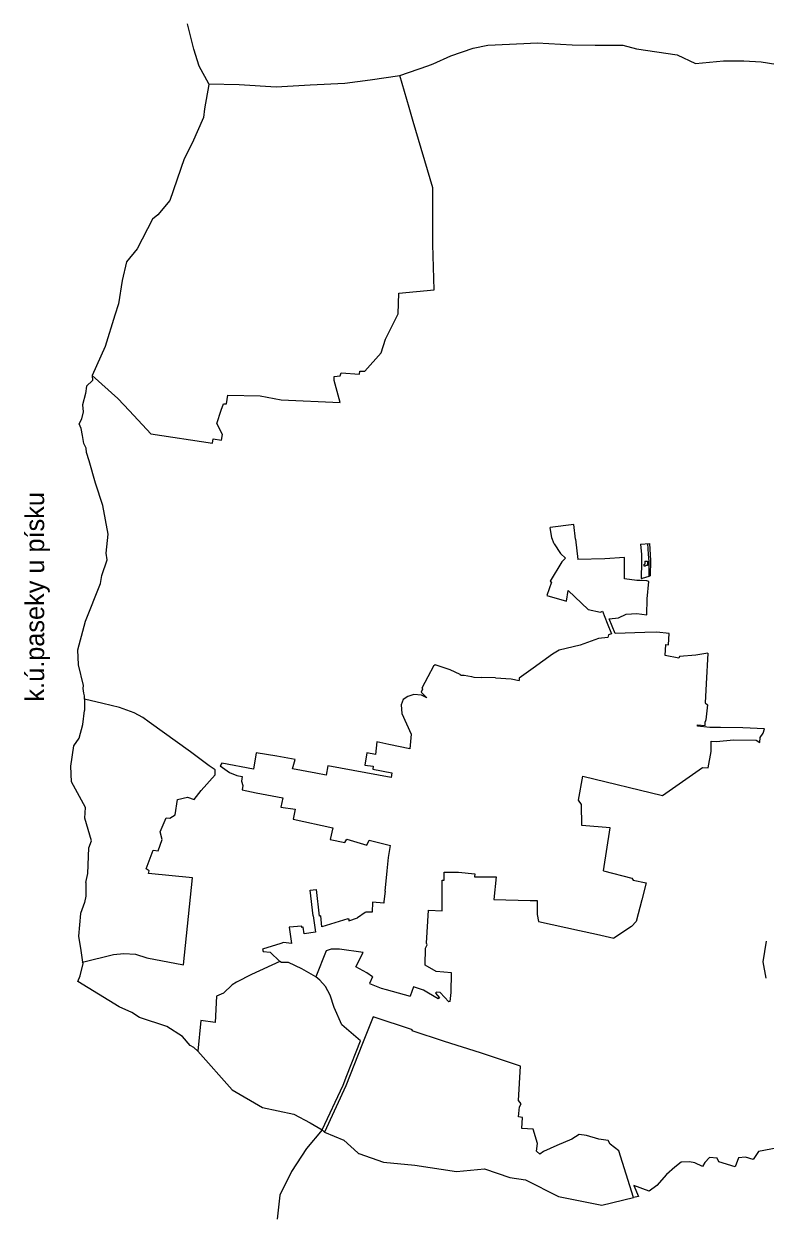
# Model space of a CAD drawing. Extents: x -764981 to -759318, y -1137368 to -1131930.
# Drawn here: x -764981 to -763217, y -1134773 to -1131930 of the extents above; entities that cross this region are included whole.
import ezdxf

# ---------------------------------------------------------------- set-up
doc = ezdxf.new("R2010")
doc.units = 0
for name, color, linetype in [('Vrstva 40', 7, 'Continuous'), ('Vrstva 41', 7, 'Continuous'), ('Vrstva 42', 7, 'Continuous'), ('Vrstva 43', 7, 'Continuous'), ('Vrstva 44', 7, 'Continuous'), ('Vrstva 45', 7, 'Continuous')]:
    doc.layers.add(name, color=color, linetype=linetype)

msp = doc.modelspace()

# ---------------------------------------------------------------- linework, layer by layer
at = {"layer": 'Vrstva 40'}
for p, q in [((-763668, -1133155.9), (-763662.7, -1133204.2)), ((-764509.7, -1133688.5), (-764513.8, -1133695.3)), ((-764461.7, -1133752.2), (-764428, -1133759.7)), ((-764369.8, -1134117.9), (-764413, -1134131.2)), ((-764413, -1134131.2), (-764411.2, -1134137)), ((-764411.2, -1134137), (-764394.7, -1134138.4)), ((-764394.7, -1134138.4), (-764372, -1134160.7)), ((-764261.9, -1134135.1), (-764285.9, -1134197.1)), ((-764054, -1134221.1), (-764061.9, -1134243.1))]:
    msp.add_line(p, q, dxfattribs=at)
for points in [[(-763668, -1133155.9), (-763672.7, -1133120.8), (-763728.8, -1133128.2)], [(-763719.5, -1133166.6), (-763724.5, -1133152.5), (-763728.8, -1133128.2)], [(-763719.5, -1133166.6), (-763703.7, -1133189.7), (-763692.5, -1133201), (-763701.1, -1133209.4), (-763728.7, -1133255.4)], [(-763552, -1133207.3), (-763552, -1133199.6), (-763598.3, -1133202.6), (-763662.7, -1133204.2)], [(-763551.7, -1133249.9), (-763552, -1133210.2), (-763552, -1133207.3)], [(-763728.7, -1133255.4), (-763725.7, -1133257.7), (-763736.7, -1133290.2), (-763690, -1133303.3), (-763685.5, -1133278.1), (-763638.2, -1133323), (-763609.2, -1133329.6)], [(-763493.8, -1133256.8), (-763498.6, -1133255.1), (-763514.5, -1133254.2), (-763522.8, -1133253.8), (-763551.7, -1133249.9)], [(-763498.8, -1133336.1), (-763497.5, -1133297.4), (-763493.8, -1133256.8)], [(-763609.2, -1133329.6), (-763604.4, -1133327.4)], [(-763604.4, -1133327.4), (-763592.9, -1133355.5), (-763582.4, -1133381.3), (-763590.2, -1133383.3), (-763591.8, -1133389.9)], [(-763588.3, -1133345.2), (-763566.2, -1133342.8), (-763547.9, -1133334), (-763522.1, -1133332.6), (-763498.8, -1133336.1)], [(-763445.6, -1133380), (-763475.1, -1133377), (-763503.1, -1133377.9), (-763574.3, -1133380.1), (-763588.3, -1133345.2)], [(-763591.8, -1133389.9), (-763613.9, -1133392.1), (-763657.6, -1133407.8), (-763673.9, -1133411.9)], [(-763353.4, -1133426.8), (-763381.8, -1133432), (-763421.3, -1133434.9), (-763422.7, -1133438.7), (-763454.7, -1133432.7), (-763453.2, -1133406.6), (-763447.1, -1133406.9), (-763445.6, -1133380)], [(-763722.7, -1133429.6), (-763768.9, -1133462.9), (-763802.1, -1133486.8), (-763802.4, -1133491.7)], [(-763673.9, -1133411.9), (-763707.1, -1133419.6), (-763722.7, -1133429.6)], [(-763353.4, -1133426.8), (-763357.4, -1133499.9)], [(-763942.9, -1133478.1), (-763966.2, -1133466.6), (-764002.3, -1133454.5), (-764006.6, -1133457.8), (-764019.8, -1133483.4)], [(-764019.8, -1133483.4), (-764034, -1133510), (-764032.3, -1133513), (-764035.7, -1133519.6), (-764022.4, -1133532.9)], [(-763942.9, -1133478.1), (-763940.7, -1133479.2), (-763933.2, -1133479.2), (-763915.8, -1133482.7), (-763910.1, -1133483.8), (-763890.9, -1133485.1)], [(-763859.1, -1133485.8), (-763890.9, -1133485.1)], [(-763859.1, -1133485.8), (-763821.1, -1133488.4), (-763802.4, -1133491.7)], [(-763357.4, -1133499.9), (-763359.8, -1133545.2), (-763354.6, -1133550.1), (-763358.3, -1133585.9), (-763360.2, -1133590.1)], [(-764053.2, -1133525.5), (-764067.2, -1133529.9), (-764078.5, -1133537.2), (-764082.9, -1133550.3), (-764081.8, -1133570.7), (-764059.6, -1133619.4)], [(-764022.4, -1133532.9), (-764035, -1133527.3), (-764053.2, -1133525.5)], [(-763348.5, -1133603.5), (-763378.1, -1133600.9), (-763377.8, -1133597.6), (-763359.6, -1133599.2), (-763360.2, -1133590.1)], [(-763218.8, -1133606.8), (-763270.3, -1133604.4), (-763323.5, -1133603.8), (-763348.5, -1133603.5)], [(-764059.6, -1133619.4), (-764062.3, -1133654.5)], [(-763345.3, -1133636), (-763333.1, -1133637.5), (-763292.7, -1133633.4), (-763238.2, -1133633.7), (-763230.2, -1133639.2), (-763228.9, -1133627.4), (-763222, -1133617.3), (-763218.8, -1133606.8)], [(-764140.1, -1133638.5), (-764140.8, -1133638.3), (-764144.4, -1133668), (-764165.2, -1133663.9), (-764169.2, -1133693.4), (-764149.7, -1133696.1), (-764150.6, -1133702.8), (-764105.1, -1133711.8), (-764107.2, -1133722.5)], [(-764062.3, -1133654.5), (-764112.4, -1133644.3), (-764140.8, -1133638.3)], [(-763461, -1133765.4), (-763366.6, -1133699.4), (-763353.1, -1133700.1), (-763345.8, -1133660.6), (-763345.3, -1133636)], [(-764379.2, -1133672.3), (-764428, -1133664.2), (-764434.4, -1133703), (-764509.7, -1133688.5)], [(-764286, -1133712.3), (-764341.3, -1133702.2), (-764335.6, -1133680), (-764379.2, -1133672.3)], [(-764513.8, -1133695.3), (-764491.2, -1133710.7), (-764474, -1133717.7), (-764461.8, -1133720.8), (-764462.8, -1133731.3), (-764460, -1133742.2), (-764461.7, -1133752.2)], [(-764261.3, -1133717.2), (-764286, -1133712.3)], [(-764107.2, -1133722.5), (-764257.3, -1133695.2), (-764261.3, -1133717.2)], [(-763661.3, -1133776.9), (-763651.3, -1133719.6), (-763461, -1133765.4)], [(-764428, -1133759.7), (-764364.8, -1133771.3), (-764369.8, -1133793.5), (-764335, -1133798.1), (-764339.9, -1133821.9), (-764245.8, -1133842.4), (-764251.8, -1133870.2), (-764217.1, -1133877.7)], [(-763602, -1133944.6), (-763585.6, -1133842.8), (-763653.3, -1133836.9), (-763654.2, -1133787.3), (-763661.3, -1133776.9)], [(-764217.1, -1133877.7), (-764212.8, -1133869.7), (-764164.5, -1133884)], [(-764164.5, -1133884), (-764159.3, -1133871.6), (-764108.7, -1133884.6)], [(-764121.2, -1133993.6), (-764116.3, -1133944.7), (-764113.1, -1133913), (-764108.7, -1133884.6)], [(-763602, -1133944.6), (-763534.2, -1133962.4), (-763530.9, -1133967.3), (-763500.2, -1133973.4)], [(-764022.9, -1134117.2), (-764017.8, -1134038.2), (-763985.5, -1134040.2), (-763985.5, -1133967.1), (-763980.5, -1133967.1), (-763980.5, -1133948), (-763947, -1133948), (-763908.2, -1133952.1), (-763909, -1133959.5), (-763868.5, -1133959), (-763856.9, -1133958.8), (-763862.9, -1134013.1), (-763775.9, -1134015.3)], [(-763500.2, -1133973.4), (-763510.6, -1134014.1), (-763523.7, -1134065.4), (-763535.4, -1134077.6), (-763577.3, -1134104.9)], [(-764292.5, -1134052.1), (-764299.6, -1133990.8), (-764285, -1133989.1), (-764278.5, -1134052.6)], [(-764121.2, -1133993.6), (-764124.2, -1134018.2)], [(-764124.2, -1134018.2), (-764124.2, -1134021.9), (-764151.6, -1134019.6), (-764152, -1134043.3), (-764166.9, -1134043), (-764168.7, -1134044.2)], [(-763775.9, -1134015.3), (-763759.9, -1134015.3)], [(-763759.9, -1134015.3), (-763759.9, -1134048.6), (-763756.1, -1134065.8), (-763658.7, -1134086.8)], [(-764292.5, -1134052.1), (-764286.8, -1134091), (-764313.9, -1134095), (-764316.2, -1134079.3), (-764319.3, -1134079.8), (-764319.7, -1134076.7), (-764349.3, -1134079), (-764343.8, -1134117.5)], [(-764210, -1134059.1), (-764272.2, -1134078.1), (-764274.3, -1134052.3), (-764278.5, -1134052.6)], [(-764210, -1134059.1), (-764207.6, -1134059.1), (-764207.6, -1134063.8), (-764186.7, -1134057)], [(-764168.7, -1134044.2), (-764186.7, -1134057)], [(-763658.7, -1134086.8), (-763618.1, -1134095.8), (-763577.3, -1134104.9)], [(-764343.8, -1134117.5), (-764363.4, -1134115.6), (-764369.8, -1134117.9)], [(-763966.3, -1134255.4), (-763964.5, -1134234.4), (-763963.6, -1134187.7), (-763999.9, -1134184), (-764026.3, -1134169.4), (-764025.1, -1134128.6), (-764021.6, -1134121.2), (-764022.9, -1134117.2)], [(-764190.6, -1134173.2), (-764173.9, -1134139.2), (-764229.6, -1134131.5), (-764249.6, -1134131.3), (-764261.9, -1134135.1)], [(-764151.7, -1134196.9), (-764164.9, -1134187.9), (-764190.6, -1134173.2)], [(-764151.7, -1134196.9), (-764158.3, -1134213.1), (-764131.1, -1134224.2)], [(-764131.1, -1134224.2), (-764119, -1134227), (-764061.9, -1134243.1)], [(-764018, -1134236), (-764030.4, -1134228.6), (-764054, -1134221.1)], [(-763966.3, -1134255.4), (-763969.8, -1134256.8), (-763990.5, -1134234.1), (-763998.9, -1134233.8), (-764001.7, -1134235.7), (-763992.1, -1134246.7), (-763995.5, -1134249.7), (-764018, -1134236)]]:
    msp.add_lwpolyline(points, dxfattribs=at)
at = {"layer": 'Vrstva 41'}
for p, q in [((-763621.2, -1131980.7), (-763601.1, -1131980.7)), ((-764007.3, -1132024.7), (-763965.3, -1132006.2)), ((-764020, -1132029.6), (-764007.3, -1132024.7)), ((-764004.9, -1132562.2), (-764007.5, -1132454.8)), ((-764088.8, -1132570.3), (-764004.9, -1132562.2)), ((-764837, -1133362.8), (-764834.2, -1133351)), ((-764579.3, -1133961.3), (-764684.2, -1133951.1)), ((-764601.4, -1134168.4), (-764579.3, -1133961.3)), ((-764055.9, -1134323.4), (-764150, -1134291.9))]:
    msp.add_line(p, q, dxfattribs=at)
for points in [[(-763965.3, -1132006.2), (-763912.1, -1131987.6), (-763876.8, -1131980.3), (-763791.6, -1131976.4)], [(-763791.6, -1131976.4), (-763759.8, -1131974.6), (-763676.7, -1131979.4), (-763621.2, -1131980.7)], [(-763609, -1131980.7), (-763555.8, -1131980.7), (-763522.9, -1131989.2), (-763426.3, -1132003.4), (-763382.5, -1132024.3), (-763316.6, -1132017.9)], [(-764064.1, -1132128.8), (-764086.4, -1132052.7), (-764020, -1132029.6)], [(-763316.6, -1132017.9), (-763267.7, -1132017.9), (-763226.4, -1132020), (-763171.7, -1132029)], [(-764007.5, -1132454.8), (-764007.5, -1132319.6), (-764054.3, -1132162.1), (-764064.1, -1132128.8)], [(-764226.1, -1132760.1), (-764182.3, -1132763.3), (-764181.8, -1132755.8), (-764181.8, -1132755.8), (-764169.5, -1132755.8), (-764130.8, -1132712.5), (-764120.7, -1132679.6), (-764090, -1132619.7), (-764088.8, -1132570.3)], [(-764678.5, -1132905.4), (-764729.8, -1132850.1), (-764756.9, -1132821), (-764818.2, -1132766.2), (-764817.4, -1132778.5), (-764832.1, -1132792.1)], [(-764418.5, -1132815.1), (-764368.5, -1132824.2), (-764228.4, -1132830.9), (-764242.8, -1132777.9), (-764242.2, -1132768.9), (-764228.4, -1132767.2), (-764226.1, -1132760.1)], [(-764832.1, -1132792.1), (-764834, -1132808.9), (-764841.3, -1132835.8), (-764839.4, -1132852.7), (-764843.4, -1132869.6), (-764848.9, -1132881.3)], [(-764521.7, -1132880.8), (-764511, -1132849), (-764505.8, -1132833.5), (-764498.4, -1132833.8), (-764495.7, -1132813.4), (-764418.5, -1132815.1)], [(-764825.6, -1132969.8), (-764831.8, -1132949.3), (-764832.3, -1132939.3), (-764838.3, -1132928.3), (-764841.5, -1132908.9), (-764844.2, -1132892.3), (-764848.9, -1132881.3)], [(-764678.5, -1132905.4), (-764531.9, -1132927.5), (-764530.3, -1132916.9), (-764510.3, -1132919.9), (-764508.3, -1132906.6), (-764521.7, -1132880.8)], [(-764792.9, -1133075.7), (-764810.5, -1133022.7), (-764825.6, -1132969.8)], [(-764795.6, -1133242.1), (-764782.3, -1133204.6), (-764785.2, -1133189.1), (-764780, -1133143.9), (-764792.9, -1133075.7)], [(-764834.2, -1133351), (-764798.7, -1133261), (-764795.6, -1133242.1)], [(-764837.8, -1133522.5), (-764839.9, -1133511.4), (-764839, -1133503.8), (-764851.1, -1133454.6), (-764852.7, -1133419.1), (-764837, -1133362.8)], [(-764836.6, -1133536.8), (-764836.6, -1133528.5), (-764837.8, -1133522.5)], [(-764525.3, -1133704.2), (-764539.6, -1133695.3), (-764584.6, -1133661.5), (-764682.6, -1133591.1), (-764697.8, -1133580.2), (-764718.3, -1133569.2), (-764752.9, -1133556.5), (-764793.2, -1133547), (-764836.6, -1133536.8)], [(-764575.6, -1133774.8), (-764558.6, -1133753.7), (-764525.7, -1133716.6), (-764525.3, -1133704.2)], [(-764656.2, -1133852), (-764642.1, -1133819.1), (-764633.3, -1133819.5), (-764620.9, -1133811.7), (-764615.6, -1133775.1), (-764591.3, -1133770), (-764575.6, -1133774.8)], [(-764684.2, -1133951.1), (-764682.4, -1133944.7), (-764689.8, -1133940.5), (-764672.9, -1133895.6), (-764661.6, -1133897.1), (-764651.4, -1133870), (-764656.2, -1133852)], [(-763215.1, -1134112.3), (-763222.8, -1134161.4), (-763215.8, -1134200.2)], [(-764852.4, -1134208.1), (-764847, -1134194.8), (-764840, -1134165.3), (-764841.2, -1134162), (-764767.4, -1134144.2), (-764743, -1134141.2)], [(-764743, -1134141.2), (-764715.1, -1134143), (-764688.3, -1134151.6), (-764601.4, -1134168.4)], [(-764351.5, -1134162.9), (-764367.9, -1134162.9), (-764372, -1134160.7), (-764439.4, -1134191.8)], [(-764285.9, -1134197.1), (-764319.7, -1134177.7), (-764351.5, -1134162.9)], [(-764439.4, -1134191.8), (-764475, -1134209.4), (-764485.1, -1134216.3)], [(-764224.3, -1134311.1), (-764242.2, -1134269.7), (-764252.2, -1134241), (-764262.9, -1134219.7), (-764276.3, -1134205.2), (-764285.9, -1134197.1)], [(-764640.8, -1134315.1), (-764705.9, -1134294.2), (-764724, -1134281.6), (-764753.9, -1134268.1), (-764852.4, -1134208.1)], [(-764485.1, -1134216.3), (-764505.6, -1134235.7), (-764522.2, -1134243.3), (-764525.6, -1134306.1), (-764559.7, -1134300.8), (-764567, -1134374), (-764576.3, -1134365), (-764585.3, -1134360.5), (-764603, -1134338.8), (-764640.8, -1134315.1)], [(-764150, -1134291.9), (-764175.1, -1134355.4), (-764215.1, -1134456.5), (-764265.2, -1134566.3)], [(-764212.6, -1134431.5), (-764180.1, -1134349.3), (-764224.3, -1134311.1)], [(-763894.5, -1134377.9), (-763979.7, -1134350.6), (-764056.7, -1134325.9), (-764055.9, -1134323.4)], [(-763803.9, -1134491.1), (-763798.9, -1134409.9), (-763894.5, -1134377.9)], [(-764265.2, -1134566.3), (-764271.3, -1134561.3), (-764221.4, -1134455.1), (-764212.6, -1134431.5)], [(-763768.8, -1134559.7), (-763796.1, -1134558), (-763794.5, -1134532), (-763803.7, -1134530.2), (-763801.3, -1134506.7), (-763798, -1134499), (-763803.9, -1134491.1)], [(-763712.7, -1134598.7), (-763744.9, -1134612.9), (-763753.2, -1134618.9), (-763760.9, -1134612), (-763758.4, -1134593.5), (-763768.8, -1134559.7)], [(-763659.4, -1134571.9), (-763676.9, -1134583.5), (-763712.7, -1134598.7)], [(-763565.5, -1134611.3), (-763586.2, -1134595.2), (-763590.3, -1134586.8), (-763613.2, -1134583.5), (-763642.3, -1134574.6), (-763659.4, -1134571.9)], [(-763106.6, -1134638.3), (-763119.7, -1134626.1), (-763141.3, -1134595), (-763233.3, -1134612.5)], [(-763475, -1134693.4), (-763493.1, -1134707.3), (-763529.6, -1134693.7), (-763518.2, -1134719.9), (-763530.4, -1134721.9), (-763565.5, -1134611.3)], [(-763280.4, -1134627.5), (-763288.8, -1134648.9), (-763327.2, -1134637.5), (-763331, -1134628.7), (-763349.2, -1134627), (-763360.6, -1134638.7)], [(-763233.3, -1134612.5), (-763245.9, -1134631.3), (-763263.7, -1134626.5), (-763280.4, -1134627.5)], [(-763360.6, -1134638.7), (-763366.5, -1134648.1), (-763384.5, -1134639.5), (-763397.4, -1134637.6), (-763416.6, -1134638.3), (-763431.9, -1134650.1), (-763451.5, -1134667), (-763475, -1134693.4)]]:
    msp.add_lwpolyline(points, dxfattribs=at)
at = {"layer": 'Vrstva 42'}
for points in [[(-763513.5, -1133167.4), (-763492.3, -1133166.2), (-763489.9, -1133206.5), (-763490.6, -1133243), (-763493.9, -1133244.6), (-763510.1, -1133249.2)], [(-763513.5, -1133167.4), (-763511.4, -1133192.3), (-763511.1, -1133210.7), (-763512.1, -1133249.2), (-763510.1, -1133249.2)]]:
    msp.add_lwpolyline(points, dxfattribs=at)
at = {"layer": 'Vrstva 43'}
msp.add_line((-763503.4, -1133208.5), (-763503.3, -1133215), dxfattribs=at)
for points in [[(-763497, -1133166.4), (-763495.2, -1133191.4), (-763493.9, -1133208.7), (-763493.9, -1133244.6)], [(-763503.4, -1133208.5), (-763497.1, -1133208.5), (-763497.1, -1133218.1), (-763500.5, -1133218.4), (-763502.8, -1133220), (-763504.7, -1133220.1), (-763504.9, -1133215.1), (-763503.3, -1133215)]]:
    msp.add_lwpolyline(points, dxfattribs=at)
at = {"layer": 'Vrstva 44'}
for p, q in [((-764217.4, -1132071), (-764157.1, -1132062.8)), ((-764157.1, -1132062.8), (-764086.4, -1132052.7)), ((-764540.8, -1132073.7), (-764551.3, -1132132)), ((-764540.6, -1132072.7), (-764540.8, -1132073.7)), ((-764540.6, -1132072.7), (-764468.9, -1132073.9)), ((-764468.9, -1132073.9), (-764380.6, -1132079.5)), ((-764380.6, -1132079.5), (-764299.9, -1132074.8)), ((-764299.9, -1132074.8), (-764217.4, -1132071)), ((-764553.8, -1132152.9), (-764580.7, -1132214)), ((-764551.3, -1132132), (-764553.8, -1132152.9)), ((-764580.7, -1132214), (-764599.3, -1132250.7)), ((-764599.3, -1132250.7), (-764633.8, -1132349.8)), ((-764633.8, -1132349.8), (-764662.3, -1132384.2)), ((-764675, -1132394.6), (-764711.3, -1132465.4)), ((-764662.3, -1132384.2), (-764675, -1132394.6)), ((-764711.3, -1132465.4), (-764737, -1132496)), ((-764737, -1132496), (-764746.7, -1132540.3)), ((-764746.7, -1132540.3), (-764755.3, -1132596)), ((-764755.3, -1132596), (-764764.1, -1132623)), ((-764764.1, -1132623), (-764787.2, -1132697.4)), ((-764787.2, -1132697.4), (-764818.2, -1132766.2)), ((-764836.6, -1133536.8), (-764836.2, -1133563.1)), ((-764833, -1133972.5), (-764833, -1134005)), ((-764836.6, -1134020.5), (-764845.9, -1134046.1)), ((-764833, -1134005), (-764836.6, -1134020.5)), ((-764845.9, -1134046.1), (-764851, -1134100)), ((-764851, -1134100), (-764845.4, -1134134.5)), ((-764845.4, -1134134.5), (-764841.2, -1134162)), ((-764567, -1134374), (-764485, -1134466)), ((-764485, -1134466), (-764412.9, -1134508.1)), ((-764412.9, -1134508.1), (-764338.7, -1134524.1)), ((-764338.7, -1134524.1), (-764300, -1134544.8)), ((-764300, -1134544.8), (-764271.3, -1134561.3)), ((-763824.3, -1134674.8), (-763787.4, -1134680.4)), ((-763787.4, -1134680.4), (-763709.2, -1134719.8)), ((-763709.2, -1134719.8), (-763605.4, -1134740.7)), ((-763605.4, -1134740.7), (-763530.4, -1134721.9))]:
    msp.add_line(p, q, dxfattribs=at)
for points in [[(-764833, -1133972.5), (-764828.3, -1133951.3), (-764826, -1133890.5), (-764820, -1133873.5), (-764836.1, -1133819.2), (-764833.8, -1133794.3), (-764867.4, -1133733.5), (-764869.2, -1133695.8), (-764862.3, -1133647.4), (-764849, -1133629.5), (-764840.3, -1133596.8), (-764836.2, -1133563.1)], [(-764265.2, -1134566.3), (-764219.8, -1134585.9), (-764186.1, -1134616.2), (-764184.8, -1134617.3)], [(-764184.8, -1134617.3), (-764184.1, -1134617.6), (-764125.2, -1134638.2), (-764050.7, -1134645.1), (-763951.2, -1134660.6), (-763884.6, -1134654.1), (-763824.3, -1134674.8)]]:
    msp.add_lwpolyline(points, dxfattribs=at)
at = {"layer": 'Vrstva 45'}
for points in [[(-764540.6, -1132072.7), (-764563.7, -1132030.1), (-764576.5, -1131990.3), (-764591.4, -1131929.9)], [(-764271.3, -1134561.3), (-764308.1, -1134605.5), (-764344.1, -1134660.2), (-764372.1, -1134716.6), (-764377.8, -1134773.5)]]:
    msp.add_lwpolyline(points, dxfattribs=at)

# ---------------------------------------------------------------- texts
msp.add_text('k.ú.paseky u písku', height=45, rotation=90, dxfattribs=at).set_placement((-764932.5, -1133542.1))

doc.saveas('drawing.dxf')
